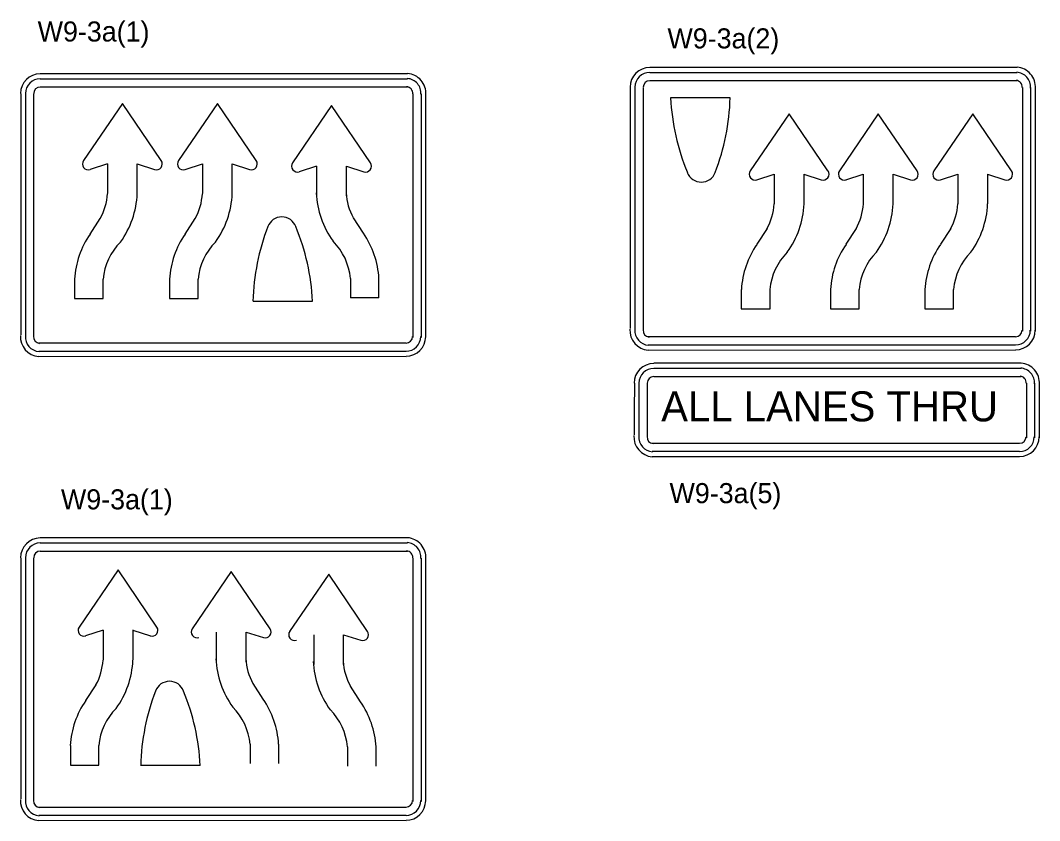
# Model space of a CAD drawing. Extents: x 1531.44 to 1538.58, y 1529.59 to 1539.3.
# Drawn here: x 1531.558 to 1534.607, y 1531.653 to 1534.046 of the extents above; entities that cross this region are included whole.
import ezdxf

# ---------------------------------------------------------------- set-up
doc = ezdxf.new("R2010")
doc.units = 0
doc.layers.add('DETL-LINE', color=7, linetype='Continuous')
doc.layers.add('DETL-NOTE', color=7, linetype='Continuous')

msp = doc.modelspace()

# ---------------------------------------------------------------- linework, layer by layer
at = {"layer": 'DETL-LINE'}
for p, q in [((1532.7167, 1533.887), (1531.618, 1533.887)), ((1534.5396, 1533.9059), (1533.4409, 1533.9059)), ((1533.4409, 1533.891), (1534.5396, 1533.891)), ((1531.618, 1533.872), (1532.7167, 1533.872)), ((1533.4409, 1533.8663), (1534.5396, 1533.8663)), ((1533.4409, 1533.866), (1533.4409, 1533.8663)), ((1531.5595, 1533.8263), (1531.5595, 1533.1064)), ((1531.5744, 1533.1033), (1531.5744, 1533.8263)), ((1531.5991, 1533.1016), (1531.5991, 1533.8263)), ((1531.618, 1533.8474), (1532.7167, 1533.8474)), ((1531.618, 1533.8471), (1531.618, 1533.8474)), ((1532.7325, 1533.8263), (1532.7325, 1533.0985)), ((1532.7572, 1533.8263), (1532.7572, 1533.0985)), ((1532.7712, 1533.0985), (1532.7712, 1533.8263)), ((1533.3824, 1533.8452), (1533.3824, 1533.1254)), ((1533.3973, 1533.1222), (1533.3973, 1533.8452)), ((1533.422, 1533.1205), (1533.422, 1533.8452)), ((1534.5554, 1533.8452), (1534.5554, 1533.1174)), ((1534.58, 1533.8452), (1534.58, 1533.1174)), ((1534.5941, 1533.1174), (1534.5941, 1533.8452)), ((1531.8637, 1533.7976), (1531.7475, 1533.6269)), ((1531.9798, 1533.6269), (1531.8637, 1533.7976)), ((1532.1479, 1533.7976), (1532.0309, 1533.6269)), ((1532.2641, 1533.6269), (1532.1479, 1533.7976)), ((1532.4894, 1533.7915), (1532.3723, 1533.6199)), ((1532.6055, 1533.6199), (1532.4894, 1533.7915)), ((1533.6818, 1533.8144), (1533.5031, 1533.8144)), ((1533.8578, 1533.7668), (1533.7416, 1533.5961)), ((1533.9739, 1533.5961), (1533.8578, 1533.7668)), ((1534.1244, 1533.7668), (1534.0082, 1533.5961)), ((1534.2406, 1533.5961), (1534.1244, 1533.7668)), ((1534.4069, 1533.7668), (1534.2907, 1533.5961)), ((1534.523, 1533.5961), (1534.4069, 1533.7668)), ((1531.8188, 1533.6172), (1531.7669, 1533.6005)), ((1531.8188, 1533.6172), (1531.8188, 1533.5284)), ((1531.9077, 1533.6172), (1531.9596, 1533.6005)), ((1531.9077, 1533.5284), (1531.9077, 1533.6172)), ((1532.0511, 1533.6005), (1532.103, 1533.6172)), ((1532.103, 1533.6172), (1532.103, 1533.5284)), ((1532.1919, 1533.5284), (1532.1919, 1533.6172)), ((1532.1919, 1533.6172), (1532.2438, 1533.6005)), ((1532.4445, 1533.6102), (1532.3926, 1533.5935)), ((1532.4445, 1533.6102), (1532.4445, 1533.5213)), ((1532.5334, 1533.5213), (1532.5334, 1533.6102)), ((1532.5334, 1533.6102), (1532.5853, 1533.5935)), ((1532.5853, 1533.5935), (1532.5856, 1533.5937)), ((1533.761, 1533.5697), (1533.8129, 1533.5864)), ((1533.8129, 1533.5864), (1533.8129, 1533.4976)), ((1533.9018, 1533.5864), (1533.9537, 1533.5697)), ((1533.9026, 1533.4976), (1533.9026, 1533.5864)), ((1534.0276, 1533.5697), (1534.0795, 1533.5864)), ((1534.0795, 1533.5864), (1534.0795, 1533.4976)), ((1534.1684, 1533.5864), (1534.2203, 1533.5697)), ((1534.1693, 1533.4976), (1534.1693, 1533.5864)), ((1534.3101, 1533.5697), (1534.362, 1533.5864)), ((1534.362, 1533.5864), (1534.362, 1533.4976)), ((1534.4509, 1533.5864), (1534.5028, 1533.5697)), ((1534.4518, 1533.4976), (1534.4518, 1533.5864)), ((1531.908, 1533.5279), (1531.9077, 1533.5284)), ((1532.4436, 1533.5292), (1532.4445, 1533.5301)), ((1532.4436, 1533.5275), (1532.4445, 1533.5284)), ((1532.4436, 1533.5257), (1532.4445, 1533.5266)), ((1532.4436, 1533.524), (1532.4445, 1533.5248)), ((1532.4436, 1533.5231), (1532.4445, 1533.5231)), ((1532.4436, 1533.5213), (1532.4445, 1533.5213)), ((1533.9022, 1533.4974), (1533.9026, 1533.4976)), ((1534.1688, 1533.4974), (1534.1693, 1533.4976)), ((1534.4513, 1533.4974), (1534.4518, 1533.4976)), ((1531.7669, 1533.4069), (1531.7968, 1533.4536)), ((1532.0511, 1533.4069), (1532.081, 1533.4536)), ((1532.5844, 1533.4096), (1532.5545, 1533.4562)), ((1533.7918, 1533.4236), (1533.761, 1533.377)), ((1534.0584, 1533.4236), (1534.0276, 1533.377)), ((1534.3409, 1533.4236), (1534.3101, 1533.377)), ((1531.7202, 1533.2723), (1531.7202, 1533.2142)), ((1531.8065, 1533.2142), (1531.8065, 1533.2723)), ((1532.0045, 1533.2723), (1532.0045, 1533.2142)), ((1532.0898, 1533.2142), (1532.0898, 1533.2723)), ((1532.5457, 1533.2749), (1532.5457, 1533.2168)), ((1532.631, 1533.2168), (1532.631, 1533.2749)), ((1533.7143, 1533.2415), (1533.7143, 1533.1834)), ((1533.8006, 1533.1834), (1533.8006, 1533.2415)), ((1533.981, 1533.2415), (1533.981, 1533.1834)), ((1534.0672, 1533.1834), (1534.0672, 1533.2415)), ((1534.2634, 1533.2415), (1534.2634, 1533.1834)), ((1534.3497, 1533.1834), (1534.3497, 1533.2415)), ((1531.7202, 1533.2142), (1531.8065, 1533.2142)), ((1532.0045, 1533.2142), (1532.0898, 1533.2142)), ((1532.631, 1533.2168), (1532.5457, 1533.2168)), ((1532.631, 1533.2168), (1532.631, 1533.2168)), ((1532.2544, 1533.2063), (1532.4322, 1533.2063)), ((1532.4322, 1533.2063), (1532.4324, 1533.2066)), ((1533.7143, 1533.1834), (1533.8006, 1533.1834)), ((1533.981, 1533.1834), (1534.0672, 1533.1834)), ((1534.2634, 1533.1834), (1534.3497, 1533.1834)), ((1534.5346, 1533.0998), (1533.436, 1533.0998)), ((1532.7118, 1533.0809), (1531.6132, 1533.0809)), ((1534.5346, 1533.0752), (1533.436, 1533.0752)), ((1533.436, 1533.0611), (1534.5346, 1533.0602)), ((1532.7118, 1533.0563), (1531.6132, 1533.0563)), ((1531.6132, 1533.0422), (1532.7118, 1533.0413)), ((1534.5514, 1533.0208), (1533.4529, 1533.0208)), ((1533.4529, 1533.0059), (1534.5514, 1533.0059)), ((1533.4529, 1532.9812), (1534.5514, 1532.9812)), ((1533.4529, 1532.9811), (1533.4529, 1532.9812)), ((1533.3951, 1532.961), (1533.3942, 1532.8783)), ((1533.4092, 1532.8783), (1533.4092, 1532.961)), ((1533.4338, 1532.8783), (1533.4338, 1532.961)), ((1534.5672, 1532.961), (1534.5672, 1532.8783)), ((1534.5919, 1532.961), (1534.5919, 1532.8783)), ((1534.6068, 1532.8783), (1534.6068, 1532.961)), ((1533.3942, 1532.8783), (1533.3942, 1532.807)), ((1533.4092, 1532.8035), (1533.4092, 1532.8783)), ((1533.4338, 1532.8017), (1533.4338, 1532.8783)), ((1534.5672, 1532.8783), (1534.5672, 1532.7982)), ((1534.5919, 1532.8783), (1534.5919, 1532.7982)), ((1534.606, 1532.7982), (1534.6068, 1532.8783)), ((1534.5466, 1532.7815), (1533.4479, 1532.7815)), ((1534.5466, 1532.7568), (1533.4479, 1532.7568)), ((1533.4479, 1532.7419), (1534.5466, 1532.7419)), ((1532.7167, 1532.4989), (1531.618, 1532.4989)), ((1531.618, 1532.484), (1532.7167, 1532.484)), ((1531.618, 1532.4593), (1532.7167, 1532.4593)), ((1531.618, 1532.459), (1531.618, 1532.4593)), ((1531.5595, 1532.4382), (1531.5595, 1531.7184)), ((1531.5744, 1531.7152), (1531.5744, 1532.4382)), ((1531.5991, 1531.7135), (1531.5991, 1532.4382)), ((1532.7325, 1532.4382), (1532.7325, 1531.7104)), ((1532.7572, 1532.4382), (1532.7572, 1531.7104)), ((1532.7712, 1531.7104), (1532.7712, 1532.4382)), ((1531.8505, 1532.4028), (1531.7343, 1532.2321)), ((1531.9666, 1532.2321), (1531.8505, 1532.4028)), ((1532.1893, 1532.3984), (1532.0722, 1532.2268)), ((1532.3054, 1532.2268), (1532.1893, 1532.3984)), ((1532.4806, 1532.3905), (1532.3635, 1532.2189)), ((1532.5967, 1532.2189), (1532.4806, 1532.3905)), ((1531.8056, 1532.2224), (1531.7537, 1532.2057)), ((1531.8056, 1532.2224), (1531.8056, 1532.1336)), ((1531.8945, 1532.2224), (1531.9473, 1532.2057)), ((1531.8954, 1532.2224), (1531.8945, 1532.2224)), ((1531.8954, 1532.1336), (1531.8954, 1532.2224)), ((1532.1444, 1532.2171), (1532.1444, 1532.1282)), ((1532.2333, 1532.1282), (1532.2333, 1532.2171)), ((1532.2333, 1532.2171), (1532.2852, 1532.2004)), ((1532.4357, 1532.2092), (1532.4357, 1532.1204)), ((1532.5246, 1532.1204), (1532.5246, 1532.2092)), ((1532.5246, 1532.2092), (1532.5765, 1532.1925)), ((1532.2852, 1532.2004), (1532.2855, 1532.2006)), ((1532.5765, 1532.1925), (1532.5768, 1532.1928)), ((1531.7845, 1532.0588), (1531.7537, 1532.0121)), ((1532.2843, 1532.0165), (1532.2544, 1532.0631)), ((1532.5756, 1532.0086), (1532.5457, 1532.0552)), ((1531.7079, 1531.8775), (1531.7079, 1531.8194)), ((1531.7933, 1531.8194), (1531.7933, 1531.8775)), ((1532.2456, 1531.8818), (1532.2456, 1531.8238)), ((1532.331, 1531.8238), (1532.331, 1531.8818)), ((1532.5369, 1531.874), (1532.5369, 1531.8159)), ((1532.6222, 1531.8159), (1532.6222, 1531.874)), ((1531.7079, 1531.8194), (1531.7933, 1531.8194)), ((1532.096, 1531.8176), (1531.9182, 1531.8176)), ((1532.331, 1531.8238), (1532.331, 1531.8238)), ((1532.6222, 1531.8159), (1532.6222, 1531.8159)), ((1532.7118, 1531.6928), (1531.6132, 1531.6928)), ((1532.7118, 1531.6682), (1531.6132, 1531.6682)), ((1531.6132, 1531.6541), (1532.7118, 1531.6532))]:
    msp.add_line(p, q, dxfattribs=at)
for centre, radius, start, end in [((1531.618, 1533.8274), 0.059, 89.9896, 179.9896), ((1532.7123, 1533.8284), 0.059, 355.9351, 85.9351), ((1533.4409, 1533.8464), 0.059, 89.9896, 179.9896), ((1533.4409, 1533.8464), 0.0443, 89.9896, 179.9896), ((1534.5352, 1533.8473), 0.0443, 355.9351, 85.9351), ((1534.5352, 1533.8473), 0.059, 355.9351, 85.9351), ((1531.618, 1533.8274), 0.0443, 89.9896, 179.9896), ((1532.7123, 1533.8284), 0.0443, 355.9351, 85.9351), ((1533.4409, 1533.8464), 0.0197, 89.9896, 179.9896), ((1534.5352, 1533.8473), 0.0197, 355.9351, 85.9351), ((1531.618, 1533.8274), 0.0197, 89.9896, 179.9896), ((1532.7123, 1533.8284), 0.0197, 355.9351, 85.9351), ((1534.1708, 1533.8478), 0.6685, 182.8441, 202.5167), ((1533.013, 1533.8325), 0.6685, 338.9042, 358.476), ((1531.7616, 1533.6171), 0.0175, 145.7397, 288), ((1531.9654, 1533.6171), 0.0175, 252, 34.2603), ((1532.0457, 1533.6171), 0.0175, 145.7397, 288), ((1532.2494, 1533.6171), 0.0175, 252, 34.2603), ((1532.3872, 1533.6104), 0.0175, 145.7397, 288), ((1532.591, 1533.6104), 0.0175, 252, 34.2603), ((1533.595, 1533.6073), 0.0446, 200.3641, 339.6359), ((1533.7558, 1533.5865), 0.0175, 145.7397, 288), ((1533.9595, 1533.5865), 0.0175, 252, 34.2603), ((1534.0224, 1533.5865), 0.0175, 145.7397, 288), ((1534.2261, 1533.5865), 0.0175, 252, 34.2603), ((1534.3049, 1533.5865), 0.0175, 145.7397, 288), ((1534.5086, 1533.5865), 0.0175, 252, 34.2603), ((1531.641, 1533.5399), 0.1784, 331.1838, 356.1678), ((1531.641, 1533.5399), 0.2674, 324.1907, 357.4446), ((1531.925, 1533.5399), 0.1784, 331.1838, 356.1678), ((1531.925, 1533.5399), 0.2674, 324.1907, 357.4446), ((1532.7105, 1533.5424), 0.2674, 182.5554, 215.8093), ((1532.7105, 1533.5424), 0.1784, 183.8322, 208.8162), ((1533.6351, 1533.5093), 0.1784, 331.1838, 356.1678), ((1533.6351, 1533.5093), 0.2674, 324.1907, 357.4446), ((1533.9017, 1533.5093), 0.1784, 331.1838, 356.1678), ((1533.9017, 1533.5093), 0.2674, 324.1907, 357.4446), ((1534.1842, 1533.5093), 0.1784, 331.1838, 356.1678), ((1534.1842, 1533.5093), 0.2674, 324.1907, 357.4446), ((1532.3404, 1533.414), 0.0446, 20.3641, 159.6359), ((1532.9224, 1533.1889), 0.6685, 158.9042, 178.476), ((1531.7646, 1533.1735), 0.6685, 2.8441, 22.5167), ((1531.9851, 1533.2567), 0.265, 145.3872, 176.6343), ((1532.2692, 1533.2567), 0.265, 145.3872, 176.6343), ((1532.3664, 1533.2592), 0.265, 3.3657, 34.6128), ((1531.9851, 1533.2567), 0.1797, 135.1307, 175.032), ((1532.2692, 1533.2567), 0.1797, 135.1307, 175.032), ((1532.3664, 1533.2592), 0.1797, 4.968, 44.8693), ((1533.9793, 1533.2261), 0.265, 145.3872, 176.6343), ((1534.2459, 1533.2261), 0.265, 145.3872, 176.6343), ((1534.5284, 1533.2261), 0.265, 145.3872, 176.6343), ((1533.9793, 1533.2261), 0.1797, 135.1307, 175.032), ((1534.2459, 1533.2261), 0.1797, 135.1307, 175.032), ((1534.5284, 1533.2261), 0.1797, 135.1307, 175.032), ((1533.4404, 1533.1191), 0.059, 175.9351, 265.9351), ((1533.4404, 1533.1191), 0.0443, 175.9351, 265.9351), ((1533.4404, 1533.1191), 0.0197, 175.9351, 265.9351), ((1534.5347, 1533.1201), 0.059, 269.9896, 359.9896), ((1534.5347, 1533.1201), 0.0443, 269.9896, 359.9896), ((1534.5347, 1533.1201), 0.0197, 269.9896, 359.9896), ((1531.6175, 1533.1002), 0.059, 175.9351, 265.9351), ((1531.6175, 1533.1002), 0.0443, 175.9351, 265.9351), ((1531.6175, 1533.1002), 0.0197, 175.9351, 265.9351), ((1532.7118, 1533.1012), 0.059, 269.9896, 359.9896), ((1532.7118, 1533.1012), 0.0443, 269.9896, 359.9896), ((1532.7118, 1533.1012), 0.0197, 269.9896, 359.9896), ((1533.4529, 1532.9614), 0.059, 89.9896, 179.9896), ((1533.4529, 1532.9614), 0.0443, 89.9896, 179.9896), ((1534.5472, 1532.9624), 0.0443, 355.9351, 85.9351), ((1534.5472, 1532.9624), 0.059, 355.9351, 85.9351), ((1533.4529, 1532.9614), 0.0197, 89.9896, 179.9896), ((1534.5472, 1532.9624), 0.0197, 355.9351, 85.9351), ((1533.4524, 1532.8003), 0.059, 175.9351, 265.9351), ((1533.4524, 1532.8003), 0.0443, 175.9351, 265.9351), ((1533.4524, 1532.8003), 0.0197, 175.9351, 265.9351), ((1534.5466, 1532.8013), 0.059, 269.9896, 359.9896), ((1534.5466, 1532.8013), 0.0443, 269.9896, 359.9896), ((1534.5466, 1532.8013), 0.0197, 269.9896, 359.9896), ((1531.618, 1532.4394), 0.059, 89.9896, 179.9896), ((1531.618, 1532.4394), 0.0443, 89.9896, 179.9896), ((1532.7123, 1532.4403), 0.0443, 355.9351, 85.9351), ((1532.7123, 1532.4403), 0.059, 355.9351, 85.9351), ((1531.618, 1532.4394), 0.0197, 89.9896, 179.9896), ((1532.7123, 1532.4403), 0.0197, 355.9351, 85.9351), ((1531.7486, 1532.2223), 0.0175, 145.7397, 288), ((1531.9523, 1532.2223), 0.0175, 252, 34.2603), ((1532.0871, 1532.2173), 0.0175, 145.7397, 288), ((1532.2909, 1532.2173), 0.0175, 252, 34.2603), ((1532.3784, 1532.2094), 0.0175, 145.7397, 288), ((1532.5822, 1532.2094), 0.0175, 252, 34.2603), ((1531.6279, 1532.145), 0.1784, 331.1838, 356.1678), ((1531.6279, 1532.145), 0.2674, 324.1907, 357.4446), ((1532.4104, 1532.1493), 0.2674, 182.5554, 215.8093), ((1532.4104, 1532.1493), 0.1784, 183.8322, 208.8162), ((1532.7017, 1532.1414), 0.2674, 182.5554, 215.8093), ((1532.7017, 1532.1414), 0.1784, 183.8322, 208.8162), ((1532.0045, 1532.0252), 0.0446, 20.3641, 159.6359), ((1532.5865, 1531.8001), 0.6685, 158.9042, 178.476), ((1531.4287, 1531.7847), 0.6685, 2.8441, 22.5167), ((1531.9721, 1531.8619), 0.265, 145.3872, 176.6343), ((1532.0663, 1531.8661), 0.1797, 4.968, 44.8693), ((1532.0663, 1531.8661), 0.265, 3.3657, 34.6128), ((1532.3576, 1531.8583), 0.265, 3.3657, 34.6128), ((1531.9721, 1531.8619), 0.1797, 135.1307, 175.032), ((1532.3576, 1531.8583), 0.1797, 4.968, 44.8693), ((1531.6175, 1531.7121), 0.059, 175.9351, 265.9351), ((1531.6175, 1531.7121), 0.0443, 175.9351, 265.9351), ((1531.6175, 1531.7121), 0.0197, 175.9351, 265.9351), ((1532.7118, 1531.7131), 0.059, 269.9896, 359.9896), ((1532.7118, 1531.7131), 0.0443, 269.9896, 359.9896), ((1532.7118, 1531.7131), 0.0197, 269.9896, 359.9896)]:
    msp.add_arc(centre, radius, start, end, dxfattribs=at)

# ---------------------------------------------------------------- texts
msp.add_text('ALL LANES THRU', height=0.08976, dxfattribs=at).set_placement((1533.475, 1532.8472))
at = {"layer": 'DETL-NOTE'}
for s, p in [('W9-3a(1)', (1531.6102, 1533.9832)), ('W9-3a(2)', (1533.4938, 1533.9626)), ('W9-3a(5)', (1533.5, 1532.6026)), ('W9-3a(1)', (1531.6798, 1532.584))]:
    msp.add_text(s, height=0.06, dxfattribs=at).set_placement(p)

doc.saveas('drawing.dxf')
